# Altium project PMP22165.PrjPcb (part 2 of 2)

## Sheet TPS650861_Bucks.SchDoc
size 431 x 279 mm; Date: Not shown in title block; ApprovedBy: Not shown in title block; CheckedBy: Not shown in title block; Author: Not shown in title block; CompanyName: Not shown in title block; Engineer: Not shown in title block; Organization: Not shown in title block; Address1: Not shown in title block; Address2: Not shown in title block; Address3: Not shown in title block; Address4: Not shown in title block; DocumentNumber: 3; Revision: Use project parameter SCH_Rev; SheetNumber: 3; SheetTotal: 4; PageSetup: Record=PageOptions¦CenterHorizontal=True¦CenterVertical=True¦PrintScale=1.00¦XCorrection=1.00¦YCorrection=1.00¦PrintKind=0¦BorderSize=5000000¦LeftOffset=0¦BottomOffset=0¦Orientation=2¦PaperLength=1000¦PaperWidth=1000¦Scale=100¦PaperSource=15¦PrintQuality=600¦MediaType=1¦DitherType=10¦PaperKind=Letter¦PrintScaleMode=1
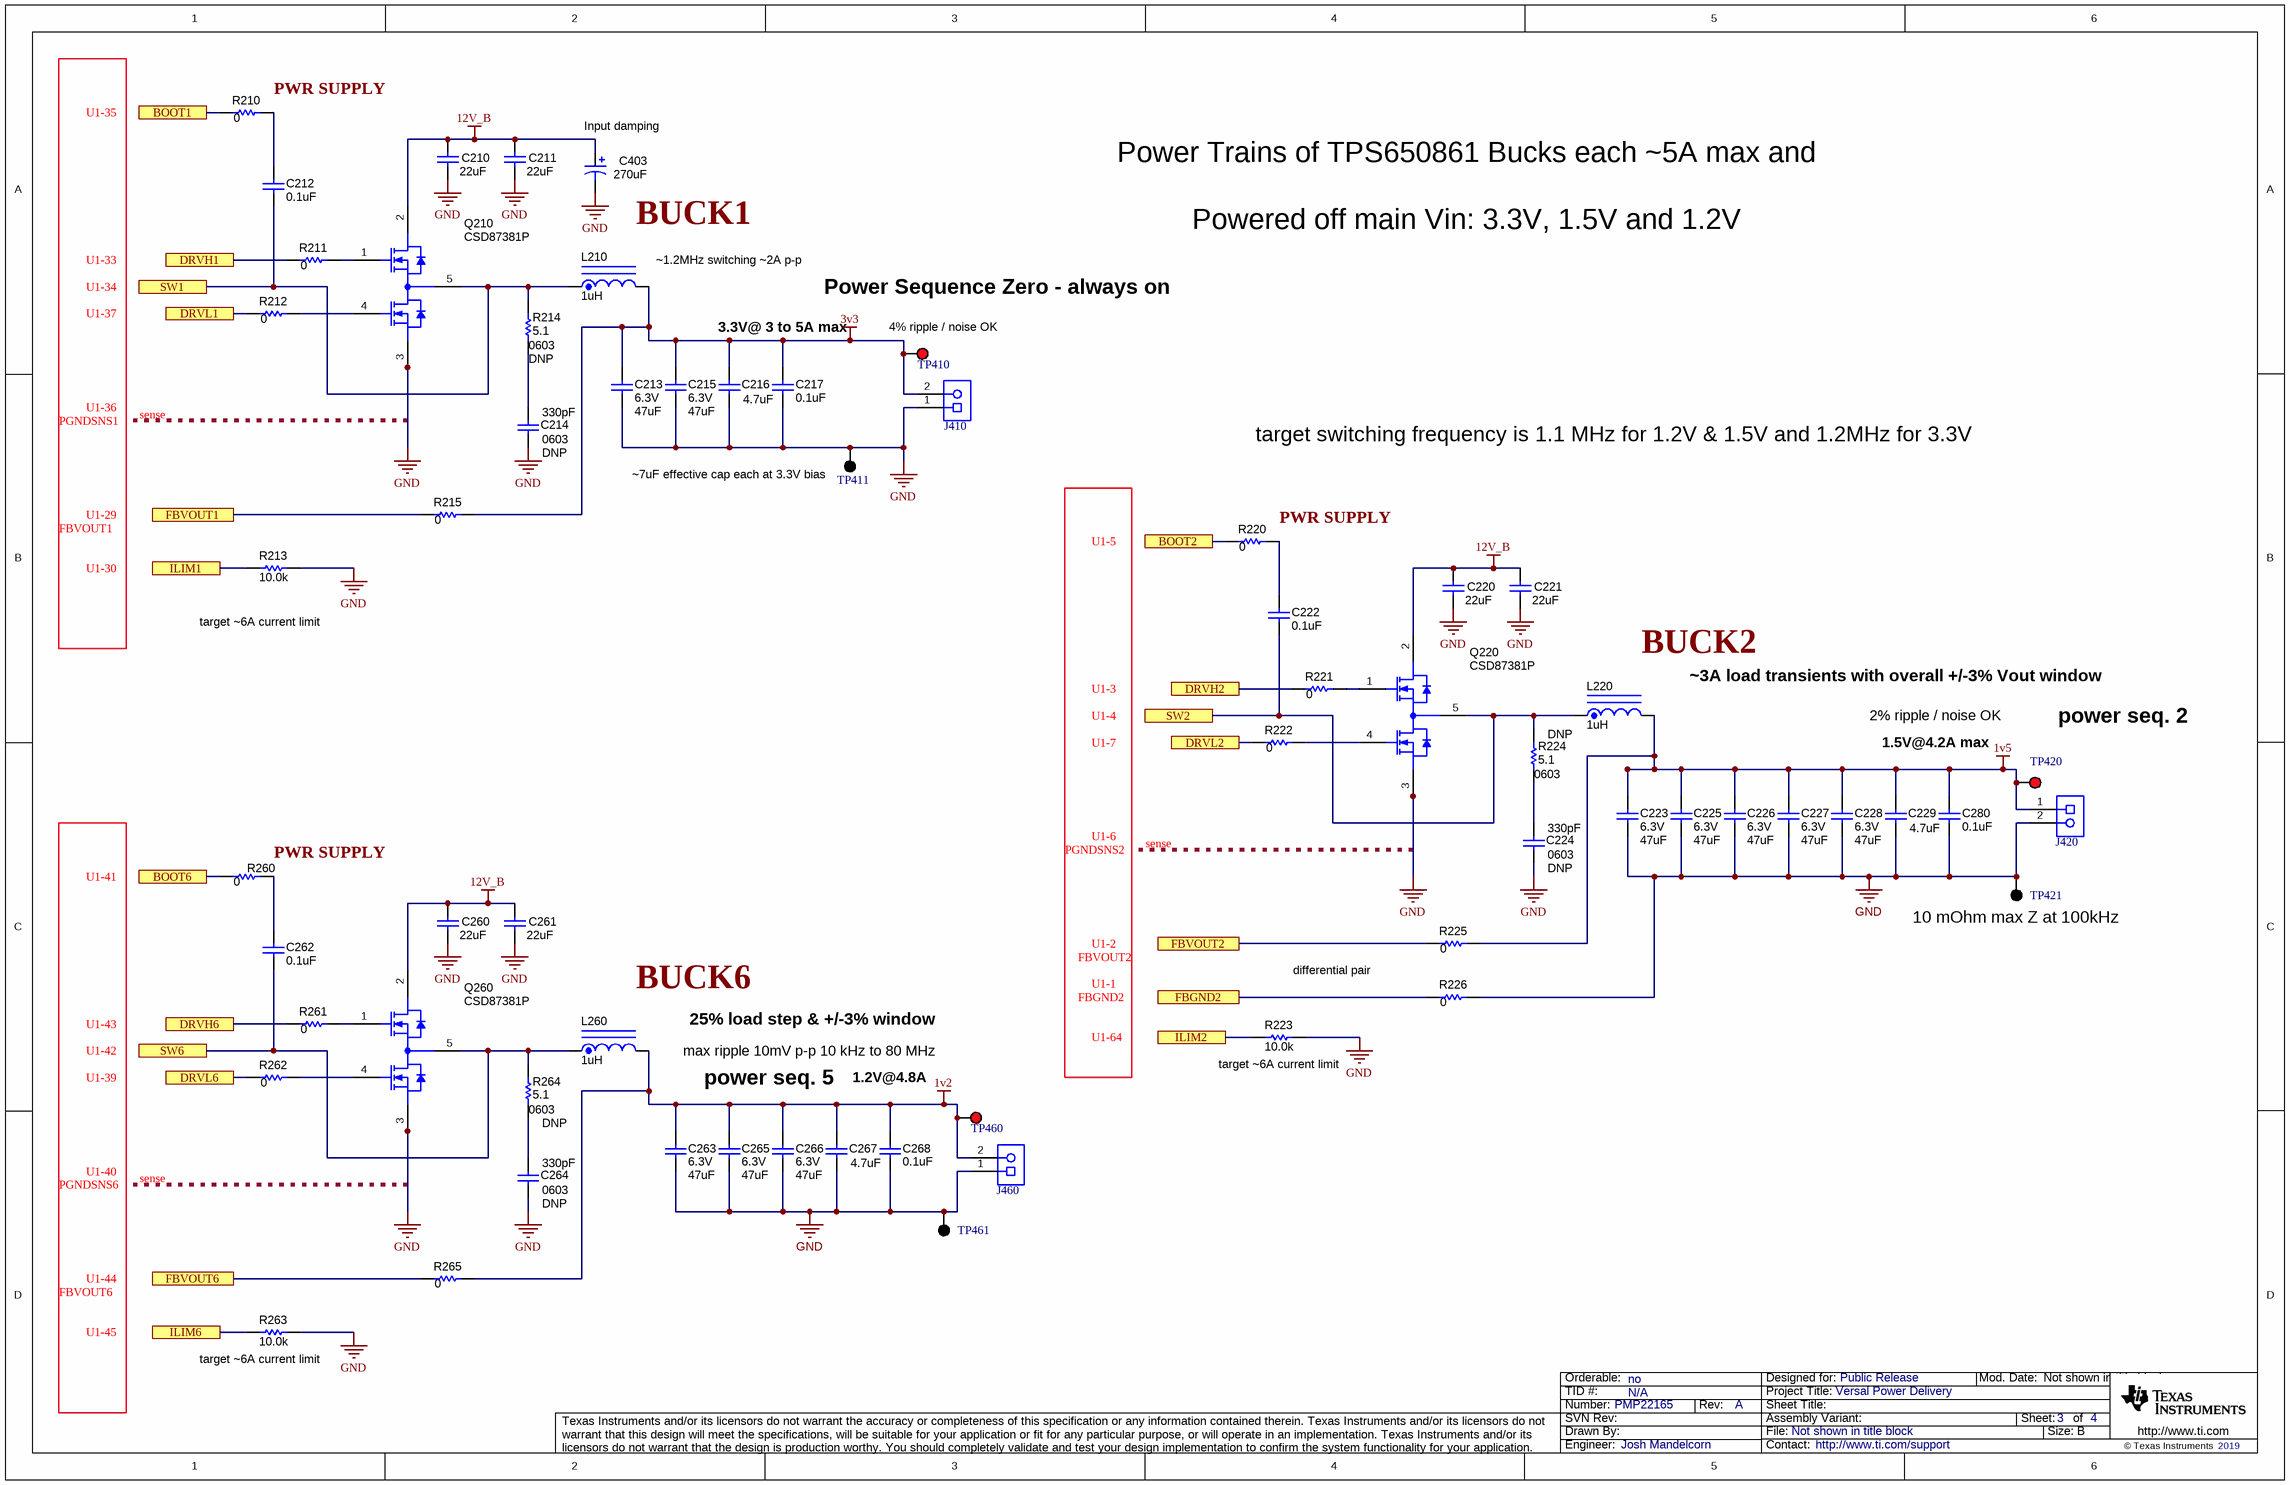
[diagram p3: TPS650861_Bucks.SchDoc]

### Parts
C210  ValueDisplayed: 22uF  [0805]  (hidden comment: C2012X5R1C226M125AC)
C211  ValueDisplayed: 22uF  [0805]  (hidden comment: C2012X5R1C226M125AC)
C212  ValueDisplayed: 0.1uF  [0402]  (hidden comment: Capacitor)
C213  VDC_V: 6.3V  ValueDisplayed: 47uF  [0805_HV]  (hidden comment: GRM21BR60J476ME15L)
C214  DNP  ValueDisplayed: 330pF  [0603]
C215  VDC_V: 6.3V  ValueDisplayed: 47uF  [0805_HV]  (hidden comment: GRM21BR60J476ME15L)
C216  value 4.7uF  [0603]  (hidden comment: Capacitor)
C217  ValueDisplayed: 0.1uF  [0402]  (hidden comment: Capacitor)
C220  ValueDisplayed: 22uF  [0805]  (hidden comment: C2012X5R1C226M125AC)
C221  ValueDisplayed: 22uF  [0805]  (hidden comment: C2012X5R1C226M125AC)
C222  ValueDisplayed: 0.1uF  [0402]  (hidden comment: Capacitor)
C223  VDC_V: 6.3V  ValueDisplayed: 47uF  [0805_HV]  (hidden comment: GRM21BR60J476ME15L)
C224  DNP  ValueDisplayed: 330pF  [0603]
C225  VDC_V: 6.3V  ValueDisplayed: 47uF  [0805_HV]  (hidden comment: GRM21BR60J476ME15L)
C226  VDC_V: 6.3V  ValueDisplayed: 47uF  [0805_HV]  (hidden comment: GRM21BR60J476ME15L)
C227  VDC_V: 6.3V  ValueDisplayed: 47uF  [0805_HV]  (hidden comment: GRM21BR60J476ME15L)
C228  VDC_V: 6.3V  ValueDisplayed: 47uF  [0805_HV]  (hidden comment: GRM21BR60J476ME15L)
C229  value 4.7uF  [0603]  (hidden comment: Capacitor)
C260  ValueDisplayed: 22uF  [0805]  (hidden comment: C2012X5R1C226M125AC)
C261  ValueDisplayed: 22uF  [0805]  (hidden comment: C2012X5R1C226M125AC)
C262  ValueDisplayed: 0.1uF  [0402]  (hidden comment: Capacitor)
C263  VDC_V: 6.3V  ValueDisplayed: 47uF  [0805_HV]  (hidden comment: GRM21BR60J476ME15L)
C264  DNP  ValueDisplayed: 330pF  [0603]
C265  VDC_V: 6.3V  ValueDisplayed: 47uF  [0805_HV]  (hidden comment: GRM21BR60J476ME15L)
C266  VDC_V: 6.3V  ValueDisplayed: 47uF  [0805_HV]  (hidden comment: GRM21BR60J476ME15L)
C267  value 4.7uF  [0603]  (hidden comment: Capacitor)
C268  ValueDisplayed: 0.1uF  [0402]  (hidden comment: Capacitor)
C280  ValueDisplayed: 0.1uF  [0402]  (hidden comment: Capacitor)
C403  ValueDisplayed: 270uF  [SM_RADIAL_10BMM]  (hidden comment: EEHZA1V271P)
J410  Receptacle_2x1  [Phoenix_1935776]  (value not drawn)
J420  Receptacle_2x1  [Phoenix_1935776]  (value not drawn)
J460  Receptacle_2x1  [Phoenix_1935776]  (value not drawn)
L210  ValueDisplayed: 1uH  [XAL4020]  (hidden comment: XAL4020-102MEB)
L220  ValueDisplayed: 1uH  [XAL4020]  (hidden comment: XAL4020-102MEB)
L260  ValueDisplayed: 1uH  [XAL4020]  (hidden comment: XAL4020-102MEB)
Q210  CSD87381P  [MPC0005A_100um]
Q220  CSD87381P  [MPC0005A_100um]
Q260  CSD87381P  [MPC0005A_100um]
R210  ValueDisplayed: 0  [0402]  (hidden comment: Resistor)
R211  ValueDisplayed: 0  [0402]  (hidden comment: Resistor)
R212  ValueDisplayed: 0  [0402]  (hidden comment: Resistor)
R213  ValueDisplayed: 10.0k  [0402]  (hidden comment: CRCW040210K0FKED)
R214  DNP  ValueDisplayed: 5.1  [0603]
R215  ValueDisplayed: 0  [0402]  (hidden comment: Resistor)
R220  ValueDisplayed: 0  [0402]  (hidden comment: Resistor)
R221  ValueDisplayed: 0  [0402]  (hidden comment: Resistor)
R222  ValueDisplayed: 0  [0402]  (hidden comment: Resistor)
R223  ValueDisplayed: 10.0k  [0402]  (hidden comment: CRCW040210K0FKED)
R224  DNP  ValueDisplayed: 5.1  [0603]
R225  ValueDisplayed: 0  [0402]  (hidden comment: Resistor)
R226  ValueDisplayed: 0  [0402]  (hidden comment: Resistor)
R260  ValueDisplayed: 0  [0402]  (hidden comment: Resistor)
R261  ValueDisplayed: 0  [0402]  (hidden comment: Resistor)
R262  ValueDisplayed: 0  [0402]  (hidden comment: Resistor)
R263  ValueDisplayed: 10.0k  [0402]  (hidden comment: CRCW040210K0FKED)
R264  DNP  ValueDisplayed: 5.1  [0603]
R265  ValueDisplayed: 0  [0402]  (hidden comment: Resistor)
TP410  5000  [Keystone5000]  (value not drawn)
TP411  5001  [Keystone5001]  (value not drawn)
TP420  5000  [Keystone5000]  (value not drawn)
TP421  5001  [Keystone5001]  (value not drawn)
TP460  5000  [Keystone5000]  (value not drawn)
TP461  5001  [Keystone5001]  (value not drawn)

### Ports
BOOT1, BOOT2, BOOT6, DRVH1, DRVH2, DRVH6, DRVL1, DRVL2, DRVL6, FBGND2, FBVOUT1, FBVOUT2, FBVOUT6, ILIM1, ILIM2, ILIM6, SW1, SW2, SW6

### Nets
1v2: C263.1 C265.1 C266.1 C267.1 C268.1 J460.2 L260.2 R265.2 TP460.1
1v5: C223.1 C225.1 C226.1 C227.1 C228.1 C229.1 C280.1 J420.1 L220.2 R225.2 TP420.1
3v3: C213.1 C215.1 C216.1 C217.1 J410.2 L210.2 R215.2 TP410.1
12V_B: C210.1 C211.1 C220.1 C221.1 C260.1 C261.1 C403.1(+) Q210.2(VIN) Q220.2(VIN) Q260.2(VIN)
GND: C210.2 C211.2 C213.2 C214.2 C215.2 C216.2 C217.2 C220.2 C221.2 C223.2 C224.2 C225.2 C226.2 C227.2 C228.2 C229.2 C260.2 C261.2 C263.2 C264.2 C265.2 C266.2 C267.2 C268.2 C280.2 C403.2(-) J410.1 J420.2 J460.1 Q210.3(PGND) Q220.3(PGND) Q260.3(PGND) R213.2 R223.2 R226.2 R263.2 TP411.1 TP421.1 TP461.1
BOOT1: R210.1 ; port BOOT1
BOOT2: R220.1 ; port BOOT2
BOOT6: R260.1 ; port BOOT6
DRVH1: R211.1 ; port DRVH1
DRVH2: R221.1 ; port DRVH2
DRVH6: R261.1 ; port DRVH6
DRVL1: R212.1 ; port DRVL1
DRVL2: R222.1 ; port DRVL2
DRVL6: R262.1 ; port DRVL6
FBGND2: R226.1 ; port FBGND2
FBVOUT1: R215.1 ; port FBVOUT1
FBVOUT2: R225.1 ; port FBVOUT2
FBVOUT6: R265.1 ; port FBVOUT6
ILIM1: R213.1 ; port ILIM1
ILIM2: R223.1 ; port ILIM2
ILIM6: R263.1 ; port ILIM6
SW1: C212.1 L210.1 Q210.5(VSW) R214.2 ; port SW1
SW2: C222.1 L220.1 Q220.5(VSW) R224.2 ; port SW2
SW6: C262.1 L260.1 Q260.5(VSW) R264.2 ; port SW6
NetC212_2: C212.2 R210.2
NetC214_1: C214.1 R214.1
NetC222_2: C222.2 R220.2
NetC224_1: C224.1 R224.1
NetC262_2: C262.2 R260.2
NetC264_1: C264.1 R264.1
NetQ210_1: Q210.1(TG) R211.2
NetQ210_4: Q210.4(BG) R212.2
NetQ220_1: Q220.1(TG) R221.2
NetQ220_4: Q220.4(BG) R222.2
NetQ260_1: Q260.1(TG) R261.2
NetQ260_4: Q260.4(BG) R262.2

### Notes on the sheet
- (near R210) PWR SUPPLY
- U1-35
- (near C403) Input damping
- Power Trains of TPS650861 Bucks each ~5A max and
- BUCK1
- Powered off main Vin: 3.3V, 1.5V and 1.2V
- U1-33
- U1-34
- (near L210) .2MHz switching |A p-p
- Power Sequence Zero - always on
- U1-37
- 3.3V@ 3 to 5A max
- (near TP410) 4% ripple / noise OK
- PGNDSNS1
- U1-36
- sense
- target switching frequency is 1.1 MHz for 1.2V & 1.5V and 1.2MHz for 3.3V
- (near TP411) ~7uF effective cap each at 3.3V bias
- FBVOUT1
- U1-29
- U1-30
- U1-5
- (near R220) PWR SUPPLY
- (near R213) target ~6A current limit
- U1-3
- BUCK2
- (near L220) ~3A load transients with overall +/-3% Vout window
- U1-4
- U1-7
- 1.5V@4.2A max
- 2% ripple / noise OK
- power seq. 2
- U1-6
- U1-41
- (near R260) PWR SUPPLY
- PGNDSNS2
- FBVOUT2
- U1-2
- differential pair
- (near TP421) 10 mOhm max Z at 100kHz
- U1-43
- BUCK6
- 25% load step & +/-3% window
- FBGND2
- U1-64
- U1-1
- U1-42
- U1-39
- power seq. 5
- max ripple 10mV p-p 10 kHz to 80 MHz
- 1.2V@4.8A
- (near R223) target ~6A current limit
- U1-40
- PGNDSNS6
- FBVOUT6
- U1-44
- U1-45
- (near R263) target ~6A current limit

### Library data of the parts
C210 C211 C220 C221 C260 C261 = CMP-0007827-2: CAP, CERM, 22 uF, 16 V, +/- 20%, X5R, 0805; Manufacturer: TDK; Polarized: N; Value: 22uF; U/M: EA; Cap_F: 22µF; Value1: Unknown; VDC_V: 16V; TaMin_C: -55°C; TaMax_C: 85°C; AEC Category: Q200; SizeArea_mm2: 2.5; SizeAreaWB_mm2: 6.75; SizeX_mm: 2; SizeY_mm: 1.25; SizeZ_mm: 1.45
C212 C217 C222 C262 C268 C280 = CMP-0006562-2: CAP, CERM, 0.1 uF, 10 V, +/- 10%, X5R, 0402; PartNumber: GRM155R61A104KA01D; Manufacturer: MuRata; Polarized: N; Value: 0.1uF; U/M: EA; Cap_F: 100nF; Value1: Unknown; VDC_V: 10V; TaMin_C: -55°C; TaMax_C: 85°C; AEC Category: Q200; SizeArea_mm2: 0.5; SizeAreaWB_mm2: 3; SizeX_mm: 1; SizeZ_mm: 0.6
C213 C215 C223 C225-C228 C263 C265 C266 = CMP-0008284-2: CAP, CERM, 47 uF, 6.3 V, +/- 20%, X5R, 0805; Manufacturer: MuRata; TaMin_C: -55°C; Polarized: N; SizeAreaWB_mm2: 6.75; Value1: Unknown; U/M: EA; Value: 47uF; TaMax_C: 85°C; SizeZ_mm: 1.45; SizeX_mm: 2; SizeY_mm: 1.25; Cap_Case: 0805; SizeArea_mm2: 2.5; Cap_F: 47µF; AEC Category: Q200
C214 C224 C264 = CMP-0007264-4: CAP, CERM, 330 pF, 100 V, +/- 5%, C0G/NP0, 0603; Manufacturer: MuRata; PartNumber: GRM1885C2A331JA01D; TaMin_C: -55°C; Polarized: N; SizeAreaWB_mm2: 4.68; Value1: Unknown; U/M: EA; Value: 330pF; TaMax_C: 125°C; SizeZ_mm: 1; SizeX_mm: 1.6; SizeY_mm: 0.8; Value2: 100V; SizeArea_mm2: 1.28; AEC Category: Q200
C216 C229 C267 = CMP-0007312-5: CAP, CERM, 4.7 uF, 6.3 V, +/- 20%, X5R, 0603; PartNumber: GRM188R60J475ME19D; Manufacturer: MuRata; Polarized: N; U/M: EA; Cap_F: 4.7µF; ESR_ohm: 1m; Value1: 0.001 ohm; VDC_V: 6.3V; TaMin_C: -55°C; TaMax_C: 85°C; AEC Category: Q200; SizeArea_mm2: 1.28; SizeAreaWB_mm2: 4.68; SizeX_mm: 1.6; SizeY_mm: 0.8; SizeZ_mm: 1
C403 = CMP-0012587-3: CAP, Polymer Hybrid, 270 uF, 35 V, +/- 20%, 20 ohm, 10x10 SMD; Manufacturer: Panasonic; Polarized: Y; CompType: Capacitor; Value: 270uF; Cap_F: 270µF; Value1: 20 ohm; VDC_V: 35V; ESR_ohm: 20; IRMS_A: 2.5A; TaMin_C: -55°C; TaMax_C: 105°C; SizeAreaWB_mm2: 159.9; SizeArea_mm2: 113.3; SizeX_mm: 11; SizeY_mm: 10.3; SizeZ_mm: 10.2; AEC Category: Q200
J410 J420 J460 = CMP-0055506-1: Terminal Block, 2x1, 5mm, Green, TH; PartNumber: 1935776; Manufacturer: Phoenix Contact; CNHeader: FALSE; CT: TRUE; Gender: Female; Green_Lifecycle: Not Set; Green_REACh: Incomplete; Pitch_mm: 5; Row_Count: 1
L210 L220 L260 = CMP-0060983-2: Inductor, Shielded, Composite, 1 µH, 8.75 A, 0.01 ohm, AEC-Q200 Grade 1, SMD; Manufacturer: Coilcraft; SizeY_mm: 4.3; Green_REACh: Incomplete; Irms: 9.6A @ 40C rise; Green_Lifecycle: Not Set; Value: 1uH; AEC Category: Q200; SizeZ_mm: 2.1; DCR_ohm: 0.01; AEC Qualified: Y; SizeArea_mm2: 18.49; Value2: 8.75A; Isat: 8.75A @ 30% inductance drop; Ind_H: 1µH; AEC Grade: 1; SizeAreaWB_mm2: 28.09
Q210 Q220 Q260 = CMP-0066162-1: Synchronous Buck NexFET Power Block II, MPC0005A (PTAB-5); Alternate Manufacturer: Texas Instruments; Alternate Manufacturer: None; SizeAreaWB_mm2: 14.0; U/M: EA; SizeZ_mm: 0.48; SizeX_mm: 2.5; SizeY_mm: 3.0; SizeArea_mm2: 7.5; CompType: IC
R210-R212 R215 R220-R222 R225 R226 R260-R262 R265 = CMP-0026822-3: RES, 0, 5%, 0.063 W, AEC-Q200 Grade 0, 0402; PartNumber: CRCW04020000Z0ED; Manufacturer: Vishay-Dale; Value: 0; Value_Code: 0000; Power_W: 63mW; Value2: 0.063W; VDC_V: 50V; TempCo: 200 ppm/C; EIA_Code: E24; AEC Category: Q200; AEC Qualified: Y; SizeArea_mm2: 0.5; SizeX_mm: 1; SizeZ_mm: 0.6
R213 R223 R263 = CMP-0025958-3: RES, 10.0 k, 1%, 0.063 W, AEC-Q200 Grade 0, 0402; Manufacturer: Vishay-Dale; Power_W: 63mW; TempCo: 100 ppm/C; Value_Code: 10k0; Value: 10.0k; EIA_Code: E96; Res_ohm: 10k; SizeX_mm: 1; SizeY_mm: 0.5; SizeZ_mm: 0.6; Value2: 0.063W; AEC Qualified: Y; VDC_V: 50V; AEC Category: Q200; AEC Grade: 0
R214 R224 R264 = CMP-0025834-4: RES, 5.1, 5%, 0.1 W, AEC-Q200 Grade 0, 0603; Manufacturer: Vishay-Dale; PartNumber: CRCW06035R10JNEA; Power_W: 100mW; TempCo: 200 ppm/C; Value_Code: 5R10; Value: 5.1; EIA_Code: E24; SizeX_mm: 1.6; SizeY_mm: 0.8; SizeZ_mm: 1; Value2: 0.1W; SizeArea_mm2: 1.28; AEC Qualified: Y; VDC_V: 75V; AEC Category: Q200; AEC Grade: 0
TP410 TP420 TP460 = CMP-0055137-1: Test Point, Miniature, Red, TH; Manufacturer: Keystone; CNHeader: FALSE; Green_Lifecycle: Active; Green_REACh: Passed; ContactFinish: Silver; CT: TRUE
TP411 TP421 TP461 = CMP-0055138-1: Test Point, Miniature, Black, TH; Manufacturer: Keystone; CNHeader: FALSE; Green_Lifecycle: Active; Green_REACh: Passed; ContactFinish: Silver; CT: TRUE

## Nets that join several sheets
0v88: TPS650861&Outputs (9 pins), PMP22165_Hardware (7 pins)
1v2: TPS650861&Outputs (C52.1 U50.46), PMP22165_Hardware (7 pins), TPS650861_Bucks (9 pins)
1v5: TPS650861&Outputs (C56.1 U50.32), PMP22165_Hardware (7 pins), TPS650861_Bucks (11 pins)
1v5_MGTAVAUX: TPS650861&Outputs (C57.1 J221.1 TP221.1 U50.31), PMP22165_Hardware (7 pins)
3v3: TPS650861&Outputs (9 pins), PMP22165_Hardware (R401.2), TPS650861_Bucks (8 pins)
3v3_SU: TPS650861&Outputs (13 pins), PMP22165_Hardware (C401.1 R402.2 R403.2 R404.2)
5v: TPS650861&Outputs (J481.4 R50.1 R51.1), PMP22165_Hardware (C412.1 J493.2 J494.1)
12V_B: TPS650861&Outputs (R55.2), PMP22165_Hardware (L400.2), TPS650861_Bucks (10 pins)
GND: TPS650861&Outputs (47 pins), PMP22165_Hardware (58 pins), TPS650861_Bucks (39 pins)
0v78_Good: TPS650861&Outputs (D99.1 J481.1 R59.1 U50.63), PMP22165_Hardware (J496.2)
3v3_Good: TPS650861&Outputs (J481.3 R65.1 U50.16), PMP22165_Hardware (J495.1)
5v_Good: TPS650861&Outputs (D99.2 J481.2 R61.1 U50.14), PMP22165_Hardware (J492.1)
BOOT1: TPS650861&Outputs (U50.35), TPS650861_Bucks (R210.1)
BOOT2: TPS650861&Outputs (U50.5), TPS650861_Bucks (R220.1)
BOOT6: TPS650861&Outputs (U50.41), TPS650861_Bucks (R260.1)
DRVH1: TPS650861&Outputs (U50.33), TPS650861_Bucks (R211.1)
DRVH2: TPS650861&Outputs (U50.3), TPS650861_Bucks (R221.1)
DRVH6: TPS650861&Outputs (U50.43), TPS650861_Bucks (R261.1)
DRVL1: TPS650861&Outputs (U50.37), TPS650861_Bucks (R212.1)
DRVL2: TPS650861&Outputs (U50.7), TPS650861_Bucks (R222.1)
DRVL6: TPS650861&Outputs (U50.39), TPS650861_Bucks (R262.1)
FBGND2: TPS650861&Outputs (U50.1), TPS650861_Bucks (R226.1)
FBVOUT1: TPS650861&Outputs (U50.29), TPS650861_Bucks (R215.1)
FBVOUT2: TPS650861&Outputs (U50.2), TPS650861_Bucks (R225.1)
FBVOUT6: TPS650861&Outputs (U50.44), TPS650861_Bucks (R265.1)
ILIM1: TPS650861&Outputs (U50.30), TPS650861_Bucks (R213.1)
ILIM2: TPS650861&Outputs (U50.64), TPS650861_Bucks (R223.1)
ILIM6: TPS650861&Outputs (U50.45), TPS650861_Bucks (R263.1)
PMB_CLK: TPS650861&Outputs (U50.58), PMP22165_Hardware (J401.9 R404.1)
PMB_DIO: TPS650861&Outputs (U50.59), PMP22165_Hardware (J401.10 R403.1)
SW1: TPS650861&Outputs (U50.34), TPS650861_Bucks (C212.1 L210.1 Q210.5 R214.2)
SW2: TPS650861&Outputs (U50.4), TPS650861_Bucks (C222.1 L220.1 Q220.5 R224.2)
SW6: TPS650861&Outputs (U50.42), TPS650861_Bucks (C262.1 L260.1 Q260.5 R264.2)

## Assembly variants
001: not fitted FID1 FID2 FID3
excluding Test: not fitted !PCB C52 C401 C402 C412 C421 C422 C451 C452 C461 C462 C471 C472 C490 C491 C493 C494 FID1 FID2 FID3 H1 H2 H3 H4 H5 H6 H7 H8 J50 J211 J221 J400 J401 J410 J420 J421 J422 J423 J430 J440 J450 J451 J452 J453 J460 J461 J462 J463 J471 J472 J473 J481 J491 J492 J493 J494 J495 J496 L400 L410 LBL1 Logo1 Logo2 Logo3 Logo4 Q420 Q450 Q460 Q470 R401 R402 R403 R404 R421 R422 R423 R424 R425 R426 R429 R451 R452 R453 R454 R455 R456 R461 R462 R463 R464 R465 R466 R471 R472 R473 R475 R476 R490 R491 R493 R494 R495 S400 TP400 U490 U491 ZZ1 ZZ2 ZZ3 ZZ4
